// Mitsubishi GX Works2 project: 中断定位   PLC: FX3U/FX3UC

PROGRAM MAIN
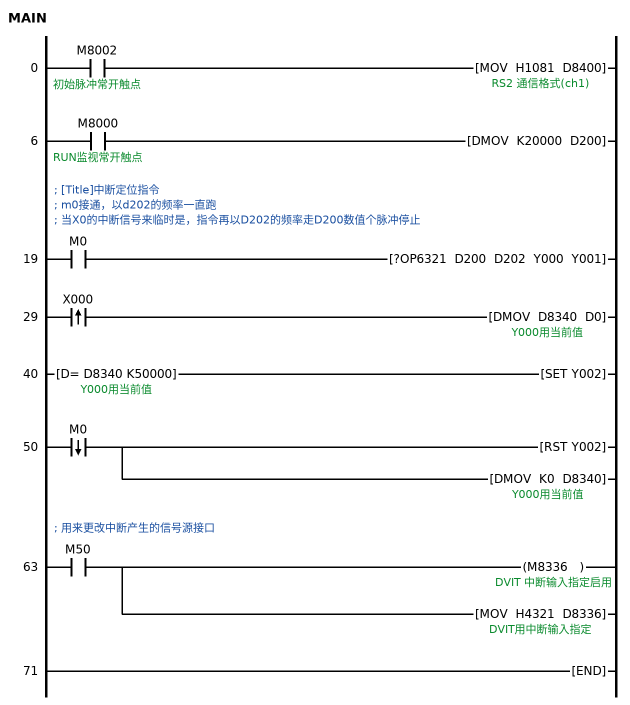
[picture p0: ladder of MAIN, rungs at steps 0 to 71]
0     LD      M8002  ; 初始脉冲常开触点
      MOV     H1081 D8400  ; RS2 通信格式(ch1)
6     LD      M8000  ; RUN监视常开触点
      DMOV    K20000 D200
; [Title]中断定位指令
; m0接通，以d202的频率一直跑
; 当X0的中断信号来临时是，指令再以D202的频率走D200数值个脉冲停止
19    LD      M0
      ?OP6321 D200 D202 Y000 Y001
29    LDP     X000
      DMOV    D8340 D0  ; Y000用当前值
40    LDD=    D8340 K50000  ; Y000用当前值
      SET     Y002
50    LDF     M0
      RST     Y002
      DMOV    K0 D8340
; 用来更改中断产生的信号源接口
63    LD      M50
      OUT     M8336  ; DVIT 中断输入指定启用
      MOV     H4321 D8336  ; DVIT用中断输入指定
71    END
END_PROGRAM

// device comments not shown above
C10  ; CCD1拍照连续不良计数
C11  ; CCD2连续不良计数
